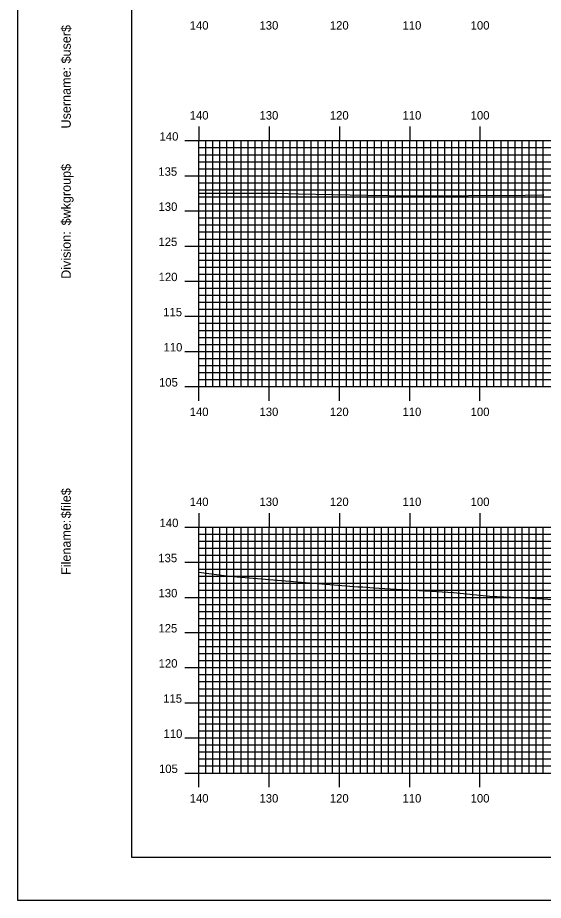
# Model space of a CAD drawing. Extents: x 1767694 to 1768037, y 442591 to 442811.
# Drawn here: x 1767693.7 to 1767768.5, y 442590.5 to 442716.2 of the extents above; entities that cross this region are included whole.
import ezdxf

# ---------------------------------------------------------------- set-up
doc = ezdxf.new("R2010")
doc.units = 0
for name, color, linetype in [('BORDER', 7, 'Continuous'), ('H_V ANNOTATION', 7, 'Continuous'), ('MAJOR', 7, 'Continuous'), ('MINOR', 7, 'Continuous'), ('PLOT BOUNDARY', 7, 'Continuous'), ('S_Roadway_Centerline', 7, 'Continuous')]:
    doc.layers.add(name, color=color, linetype=linetype)

msp = doc.modelspace()

# ---------------------------------------------------------------- linework, layer by layer
at = {"layer": 'BORDER'}
msp.add_lwpolyline([(1767709.85, 442596.67), (1768029.85, 442596.67), (1768029.85, 442806.67), (1767709.85, 442806.67)], close=True, dxfattribs=at)
at = {"layer": 'MAJOR'}
for p, q in [((1767719.45, 442700.67), (1767719.45, 442698.67)), ((1767729.45, 442700.67), (1767729.45, 442698.67)), ((1767739.45, 442700.67), (1767739.45, 442698.67)), ((1767749.45, 442700.67), (1767749.45, 442698.67)), ((1767759.45, 442700.67), (1767759.45, 442698.67)), ((1767717.45, 442698.67), (1767719.45, 442698.67)), ((1767719.45, 442698.67), (1767999.45, 442698.67)), ((1767719.45, 442663.67), (1767719.45, 442698.67)), ((1767719.45, 442663.67), (1767719.45, 442698.67)), ((1767719.45, 442698.67), (1767999.45, 442698.67)), ((1767729.45, 442663.67), (1767729.45, 442698.67)), ((1767739.45, 442663.67), (1767739.45, 442698.67)), ((1767749.45, 442663.67), (1767749.45, 442698.67)), ((1767759.45, 442663.67), (1767759.45, 442698.67)), ((1767717.45, 442693.67), (1767719.45, 442693.67)), ((1767719.45, 442693.67), (1767999.45, 442693.67)), ((1767717.45, 442688.67), (1767719.45, 442688.67)), ((1767719.45, 442688.67), (1767999.45, 442688.67)), ((1767717.45, 442683.67), (1767719.45, 442683.67)), ((1767719.45, 442683.67), (1767999.45, 442683.67)), ((1767717.45, 442678.67), (1767719.45, 442678.67)), ((1767719.45, 442678.67), (1767999.45, 442678.67)), ((1767717.45, 442673.67), (1767719.45, 442673.67)), ((1767719.45, 442673.67), (1767999.45, 442673.67)), ((1767717.45, 442668.67), (1767719.45, 442668.67)), ((1767719.45, 442668.67), (1767999.45, 442668.67)), ((1767717.45, 442663.67), (1767719.45, 442663.67)), ((1767719.45, 442663.67), (1767999.45, 442663.67)), ((1767719.45, 442663.67), (1767999.45, 442663.67)), ((1767719.45, 442661.66), (1767719.45, 442663.67)), ((1767729.45, 442661.66), (1767729.45, 442663.67)), ((1767739.45, 442661.66), (1767739.45, 442663.67)), ((1767749.45, 442661.66), (1767749.45, 442663.67)), ((1767759.45, 442661.66), (1767759.45, 442663.67)), ((1767719.45, 442645.67), (1767719.45, 442643.67)), ((1767729.45, 442645.67), (1767729.45, 442643.67)), ((1767739.45, 442645.67), (1767739.45, 442643.67)), ((1767749.45, 442645.67), (1767749.45, 442643.67)), ((1767759.45, 442645.67), (1767759.45, 442643.67)), ((1767717.45, 442643.67), (1767719.45, 442643.67)), ((1767719.45, 442643.67), (1767999.45, 442643.67)), ((1767719.45, 442608.67), (1767719.45, 442643.67)), ((1767719.45, 442608.67), (1767719.45, 442643.67)), ((1767719.45, 442643.67), (1767999.45, 442643.67)), ((1767729.45, 442608.67), (1767729.45, 442643.67)), ((1767739.45, 442608.67), (1767739.45, 442643.67)), ((1767749.45, 442608.67), (1767749.45, 442643.67)), ((1767759.45, 442608.67), (1767759.45, 442643.67)), ((1767717.45, 442638.67), (1767719.45, 442638.67)), ((1767719.45, 442638.67), (1767999.45, 442638.67)), ((1767717.45, 442633.67), (1767719.45, 442633.67)), ((1767719.45, 442633.67), (1767999.45, 442633.67)), ((1767717.45, 442628.67), (1767719.45, 442628.67)), ((1767719.45, 442628.67), (1767999.45, 442628.67)), ((1767717.45, 442623.67), (1767719.45, 442623.67)), ((1767719.45, 442623.67), (1767999.45, 442623.67)), ((1767717.45, 442618.67), (1767719.45, 442618.67)), ((1767719.45, 442618.67), (1767999.45, 442618.67)), ((1767717.45, 442613.67), (1767719.45, 442613.67)), ((1767719.45, 442613.67), (1767999.45, 442613.67)), ((1767717.45, 442608.67), (1767719.45, 442608.67)), ((1767719.45, 442608.67), (1767999.45, 442608.67)), ((1767719.45, 442608.67), (1767999.45, 442608.67)), ((1767719.45, 442606.66), (1767719.45, 442608.67)), ((1767729.45, 442606.66), (1767729.45, 442608.67)), ((1767739.45, 442606.66), (1767739.45, 442608.67)), ((1767749.45, 442606.66), (1767749.45, 442608.67)), ((1767759.45, 442606.66), (1767759.45, 442608.67))]:
    msp.add_line(p, q, dxfattribs=at)
at = {"layer": 'MINOR'}
for p, q in [((1767720.45, 442663.67), (1767720.45, 442698.67)), ((1767721.45, 442663.67), (1767721.45, 442698.67)), ((1767722.45, 442663.67), (1767722.45, 442698.67)), ((1767723.45, 442663.67), (1767723.45, 442698.67)), ((1767724.45, 442663.67), (1767724.45, 442698.67)), ((1767725.45, 442663.67), (1767725.45, 442698.67)), ((1767726.45, 442663.67), (1767726.45, 442698.67)), ((1767727.45, 442663.67), (1767727.45, 442698.67)), ((1767728.45, 442663.67), (1767728.45, 442698.67)), ((1767730.45, 442663.67), (1767730.45, 442698.67)), ((1767731.45, 442663.67), (1767731.45, 442698.67)), ((1767732.45, 442663.67), (1767732.45, 442698.67)), ((1767733.45, 442663.67), (1767733.45, 442698.67)), ((1767734.45, 442663.67), (1767734.45, 442698.67)), ((1767735.45, 442663.67), (1767735.45, 442698.67)), ((1767736.45, 442663.67), (1767736.45, 442698.67)), ((1767737.45, 442663.67), (1767737.45, 442698.67)), ((1767738.45, 442663.67), (1767738.45, 442698.67)), ((1767740.45, 442663.67), (1767740.45, 442698.67)), ((1767741.45, 442663.67), (1767741.45, 442698.67)), ((1767742.45, 442663.67), (1767742.45, 442698.67)), ((1767743.45, 442663.67), (1767743.45, 442698.67)), ((1767744.45, 442663.67), (1767744.45, 442698.67)), ((1767745.45, 442663.67), (1767745.45, 442698.67)), ((1767746.45, 442663.67), (1767746.45, 442698.67)), ((1767747.45, 442663.67), (1767747.45, 442698.67)), ((1767748.45, 442663.67), (1767748.45, 442698.67)), ((1767750.45, 442663.67), (1767750.45, 442698.67)), ((1767751.45, 442663.67), (1767751.45, 442698.67)), ((1767752.45, 442663.67), (1767752.45, 442698.67)), ((1767753.45, 442663.67), (1767753.45, 442698.67)), ((1767754.45, 442663.67), (1767754.45, 442698.67)), ((1767755.45, 442663.67), (1767755.45, 442698.67)), ((1767756.45, 442663.67), (1767756.45, 442698.67)), ((1767757.45, 442663.67), (1767757.45, 442698.67)), ((1767758.45, 442663.67), (1767758.45, 442698.67)), ((1767760.45, 442663.67), (1767760.45, 442698.67)), ((1767761.45, 442663.67), (1767761.45, 442698.67)), ((1767762.45, 442663.67), (1767762.45, 442698.67)), ((1767763.45, 442663.67), (1767763.45, 442698.67)), ((1767764.45, 442663.67), (1767764.45, 442698.67)), ((1767765.45, 442663.67), (1767765.45, 442698.67)), ((1767766.45, 442663.67), (1767766.45, 442698.67)), ((1767767.45, 442663.67), (1767767.45, 442698.67)), ((1767768.45, 442663.67), (1767768.45, 442698.67)), ((1767719.45, 442697.67), (1767999.45, 442697.67)), ((1767719.45, 442697.67), (1767721.45, 442697.67)), ((1767719.45, 442696.67), (1767999.45, 442696.67)), ((1767719.45, 442696.67), (1767721.45, 442696.67)), ((1767719.45, 442695.67), (1767999.45, 442695.67)), ((1767719.45, 442695.67), (1767721.45, 442695.67)), ((1767719.45, 442694.67), (1767999.45, 442694.67)), ((1767719.45, 442694.67), (1767721.45, 442694.67)), ((1767719.45, 442692.67), (1767999.45, 442692.67)), ((1767719.45, 442692.67), (1767721.45, 442692.67)), ((1767719.45, 442691.67), (1767999.45, 442691.67)), ((1767719.45, 442691.67), (1767721.45, 442691.67)), ((1767719.45, 442690.67), (1767999.45, 442690.67)), ((1767719.45, 442690.67), (1767721.45, 442690.67)), ((1767719.45, 442689.67), (1767999.45, 442689.67)), ((1767719.45, 442689.67), (1767721.45, 442689.67)), ((1767719.45, 442687.67), (1767999.45, 442687.67)), ((1767719.45, 442687.67), (1767721.45, 442687.67)), ((1767719.45, 442686.67), (1767999.45, 442686.67)), ((1767719.45, 442686.67), (1767721.45, 442686.67)), ((1767719.45, 442685.67), (1767999.45, 442685.67)), ((1767719.45, 442685.67), (1767721.45, 442685.67)), ((1767719.45, 442684.67), (1767999.45, 442684.67)), ((1767719.45, 442684.67), (1767721.45, 442684.67)), ((1767719.45, 442682.67), (1767999.45, 442682.67)), ((1767719.45, 442682.67), (1767721.45, 442682.67)), ((1767719.45, 442681.67), (1767999.45, 442681.67)), ((1767719.45, 442681.67), (1767721.45, 442681.67)), ((1767719.45, 442680.67), (1767999.45, 442680.67)), ((1767719.45, 442680.67), (1767721.45, 442680.67)), ((1767719.45, 442679.67), (1767999.45, 442679.67)), ((1767719.45, 442679.67), (1767721.45, 442679.67)), ((1767719.45, 442677.67), (1767999.45, 442677.67)), ((1767719.45, 442677.67), (1767721.45, 442677.67)), ((1767719.45, 442676.67), (1767999.45, 442676.67)), ((1767719.45, 442676.67), (1767721.45, 442676.67)), ((1767719.45, 442675.67), (1767999.45, 442675.67)), ((1767719.45, 442675.67), (1767721.45, 442675.67)), ((1767719.45, 442674.67), (1767999.45, 442674.67)), ((1767719.45, 442674.67), (1767721.45, 442674.67)), ((1767719.45, 442672.67), (1767999.45, 442672.67)), ((1767719.45, 442672.67), (1767721.45, 442672.67)), ((1767719.45, 442671.67), (1767999.45, 442671.67)), ((1767719.45, 442671.67), (1767721.45, 442671.67)), ((1767719.45, 442670.67), (1767999.45, 442670.67)), ((1767719.45, 442670.67), (1767721.45, 442670.67)), ((1767719.45, 442669.67), (1767999.45, 442669.67)), ((1767719.45, 442669.67), (1767721.45, 442669.67)), ((1767719.45, 442667.67), (1767999.45, 442667.67)), ((1767719.45, 442667.67), (1767721.45, 442667.67)), ((1767719.45, 442666.67), (1767999.45, 442666.67)), ((1767719.45, 442666.67), (1767721.45, 442666.67)), ((1767719.45, 442665.67), (1767999.45, 442665.67)), ((1767719.45, 442665.67), (1767721.45, 442665.67)), ((1767719.45, 442664.67), (1767999.45, 442664.67)), ((1767719.45, 442664.67), (1767721.45, 442664.67)), ((1767720.45, 442608.67), (1767720.45, 442643.67)), ((1767721.45, 442608.67), (1767721.45, 442643.67)), ((1767722.45, 442608.67), (1767722.45, 442643.67)), ((1767723.45, 442608.67), (1767723.45, 442643.67)), ((1767724.45, 442608.67), (1767724.45, 442643.67)), ((1767725.45, 442608.67), (1767725.45, 442643.67)), ((1767726.45, 442608.67), (1767726.45, 442643.67)), ((1767727.45, 442608.67), (1767727.45, 442643.67)), ((1767728.45, 442608.67), (1767728.45, 442643.67)), ((1767730.45, 442608.67), (1767730.45, 442643.67)), ((1767731.45, 442608.67), (1767731.45, 442643.67)), ((1767732.45, 442608.67), (1767732.45, 442643.67)), ((1767733.45, 442608.67), (1767733.45, 442643.67)), ((1767734.45, 442608.67), (1767734.45, 442643.67)), ((1767735.45, 442608.67), (1767735.45, 442643.67)), ((1767736.45, 442608.67), (1767736.45, 442643.67)), ((1767737.45, 442608.67), (1767737.45, 442643.67)), ((1767738.45, 442608.67), (1767738.45, 442643.67)), ((1767740.45, 442608.67), (1767740.45, 442643.67)), ((1767741.45, 442608.67), (1767741.45, 442643.67)), ((1767742.45, 442608.67), (1767742.45, 442643.67)), ((1767743.45, 442608.67), (1767743.45, 442643.67)), ((1767744.45, 442608.67), (1767744.45, 442643.67)), ((1767745.45, 442608.67), (1767745.45, 442643.67)), ((1767746.45, 442608.67), (1767746.45, 442643.67)), ((1767747.45, 442608.67), (1767747.45, 442643.67)), ((1767748.45, 442608.67), (1767748.45, 442643.67)), ((1767750.45, 442608.67), (1767750.45, 442643.67)), ((1767751.45, 442608.67), (1767751.45, 442643.67)), ((1767752.45, 442608.67), (1767752.45, 442643.67)), ((1767753.45, 442608.67), (1767753.45, 442643.67)), ((1767754.45, 442608.67), (1767754.45, 442643.67)), ((1767755.45, 442608.67), (1767755.45, 442643.67)), ((1767756.45, 442608.67), (1767756.45, 442643.67)), ((1767757.45, 442608.67), (1767757.45, 442643.67)), ((1767758.45, 442608.67), (1767758.45, 442643.67)), ((1767760.45, 442608.67), (1767760.45, 442643.67)), ((1767761.45, 442608.67), (1767761.45, 442643.67)), ((1767762.45, 442608.67), (1767762.45, 442643.67)), ((1767763.45, 442608.67), (1767763.45, 442643.67)), ((1767764.45, 442608.67), (1767764.45, 442643.67)), ((1767765.45, 442608.67), (1767765.45, 442643.67)), ((1767766.45, 442608.67), (1767766.45, 442643.67)), ((1767767.45, 442608.67), (1767767.45, 442643.67)), ((1767768.45, 442608.67), (1767768.45, 442643.67)), ((1767719.45, 442642.67), (1767999.45, 442642.67)), ((1767719.45, 442642.67), (1767721.45, 442642.67)), ((1767719.45, 442641.67), (1767999.45, 442641.67)), ((1767719.45, 442641.67), (1767721.45, 442641.67)), ((1767719.45, 442640.67), (1767999.45, 442640.67)), ((1767719.45, 442640.67), (1767721.45, 442640.67)), ((1767719.45, 442639.67), (1767999.45, 442639.67)), ((1767719.45, 442639.67), (1767721.45, 442639.67)), ((1767719.45, 442637.67), (1767999.45, 442637.67)), ((1767719.45, 442637.67), (1767721.45, 442637.67)), ((1767719.45, 442636.67), (1767999.45, 442636.67)), ((1767719.45, 442636.67), (1767721.45, 442636.67)), ((1767719.45, 442635.67), (1767999.45, 442635.67)), ((1767719.45, 442635.67), (1767721.45, 442635.67)), ((1767719.45, 442634.67), (1767999.45, 442634.67)), ((1767719.45, 442634.67), (1767721.45, 442634.67)), ((1767719.45, 442632.67), (1767999.45, 442632.67)), ((1767719.45, 442632.67), (1767721.45, 442632.67)), ((1767719.45, 442631.67), (1767999.45, 442631.67)), ((1767719.45, 442631.67), (1767721.45, 442631.67)), ((1767719.45, 442630.67), (1767999.45, 442630.67)), ((1767719.45, 442630.67), (1767721.45, 442630.67)), ((1767719.45, 442629.67), (1767999.45, 442629.67)), ((1767719.45, 442629.67), (1767721.45, 442629.67)), ((1767719.45, 442627.67), (1767999.45, 442627.67)), ((1767719.45, 442627.67), (1767721.45, 442627.67)), ((1767719.45, 442626.67), (1767999.45, 442626.67)), ((1767719.45, 442626.67), (1767721.45, 442626.67)), ((1767719.45, 442625.67), (1767999.45, 442625.67)), ((1767719.45, 442625.67), (1767721.45, 442625.67)), ((1767719.45, 442624.67), (1767999.45, 442624.67)), ((1767719.45, 442624.67), (1767721.45, 442624.67)), ((1767719.45, 442622.67), (1767999.45, 442622.67)), ((1767719.45, 442622.67), (1767721.45, 442622.67)), ((1767719.45, 442621.67), (1767999.45, 442621.67)), ((1767719.45, 442621.67), (1767721.45, 442621.67)), ((1767719.45, 442620.67), (1767999.45, 442620.67)), ((1767719.45, 442620.67), (1767721.45, 442620.67)), ((1767719.45, 442619.67), (1767999.45, 442619.67)), ((1767719.45, 442619.67), (1767721.45, 442619.67)), ((1767719.45, 442617.67), (1767999.45, 442617.67)), ((1767719.45, 442617.67), (1767721.45, 442617.67)), ((1767719.45, 442616.67), (1767999.45, 442616.67)), ((1767719.45, 442616.67), (1767721.45, 442616.67)), ((1767719.45, 442615.67), (1767999.45, 442615.67)), ((1767719.45, 442615.67), (1767721.45, 442615.67)), ((1767719.45, 442614.67), (1767999.45, 442614.67)), ((1767719.45, 442614.67), (1767721.45, 442614.67)), ((1767719.45, 442612.67), (1767999.45, 442612.67)), ((1767719.45, 442612.67), (1767721.45, 442612.67)), ((1767719.45, 442611.67), (1767999.45, 442611.67)), ((1767719.45, 442611.67), (1767721.45, 442611.67)), ((1767719.45, 442610.67), (1767999.45, 442610.67)), ((1767719.45, 442610.67), (1767721.45, 442610.67)), ((1767719.45, 442609.67), (1767999.45, 442609.67)), ((1767719.45, 442609.67), (1767721.45, 442609.67))]:
    msp.add_line(p, q, dxfattribs=at)
at = {"layer": 'PLOT BOUNDARY'}
msp.add_lwpolyline([(1767693.66, 442590.55), (1768033.66, 442590.55), (1768033.66, 442810.55), (1767693.66, 442810.55)], close=True, dxfattribs=at)
at = {"layer": 'S_Roadway_Centerline'}
for points in [[(1767719.45, 442691.21), (1767719.94, 442691.21), (1767730.63, 442691.18), (1767733.65, 442691.12), (1767743.4, 442690.92), (1767749.69, 442690.8), (1767765.88, 442690.93), (1767768.54, 442690.94)], [(1767719.45, 442637.27), (1767723.76, 442636.7), (1767739.24, 442635.38), (1767742.08, 442635.18), (1767742.78, 442635.16), (1767744.29, 442635.04), (1767755.69, 442634.36), (1767760.84, 442633.83), (1767766.88, 442633.56), (1767778.05, 442632.86)]]:
    msp.add_lwpolyline(points, dxfattribs=at)

# ---------------------------------------------------------------- texts
at = {"layer": 'BORDER'}
for s, p in [('$user$', (1767701.22, 442709.65)), ('Username:', (1767701.22, 442700.4)), ('$wkgroup$', (1767701.22, 442686.6)), ('Division:', (1767701.22, 442679)), ('$file$', (1767701.22, 442644.92)), ('Filename:', (1767701.22, 442636.86))]:
    msp.add_text(s, height=1.339, rotation=90, dxfattribs=at).set_placement(p)
at = {"layer": 'H_V ANNOTATION'}
for s, p in [('140', (1767718.15, 442714.47)), ('130', (1767728.08, 442714.47)), ('120', (1767738.09, 442714.47)), ('110', (1767748.43, 442714.47)), ('100', (1767758.13, 442714.47)), ('140', (1767718.15, 442701.67)), ('130', (1767728.08, 442701.67)), ('120', (1767738.09, 442701.67)), ('110', (1767748.43, 442701.67)), ('100', (1767758.13, 442701.67)), ('140', (1767713.86, 442698.67)), ('135', (1767713.68, 442693.67)), ('130', (1767713.71, 442688.67)), ('125', (1767713.7, 442683.67)), ('120', (1767713.73, 442678.67)), ('115', (1767714.38, 442673.67)), ('110', (1767714.42, 442668.67)), ('105', (1767713.78, 442663.67)), ('140', (1767718.15, 442659.47)), ('130', (1767728.08, 442659.47)), ('120', (1767738.09, 442659.47)), ('110', (1767748.43, 442659.47)), ('100', (1767758.13, 442659.47)), ('140', (1767718.15, 442646.67)), ('130', (1767728.08, 442646.67)), ('120', (1767738.09, 442646.67)), ('110', (1767748.43, 442646.67)), ('100', (1767758.13, 442646.67)), ('140', (1767713.86, 442643.67)), ('135', (1767713.68, 442638.67)), ('130', (1767713.71, 442633.67)), ('125', (1767713.7, 442628.67)), ('120', (1767713.73, 442623.67)), ('115', (1767714.38, 442618.67)), ('110', (1767714.42, 442613.67)), ('105', (1767713.78, 442608.67)), ('140', (1767718.15, 442604.47)), ('130', (1767728.08, 442604.47)), ('120', (1767738.09, 442604.47)), ('110', (1767748.43, 442604.47)), ('100', (1767758.13, 442604.47))]:
    msp.add_text(s, height=1.2, dxfattribs=at).set_placement(p)
at = {"layer": 'MAJOR'}
for p in [(1767719.44, 442663.67), (1767719.44, 442608.67)]:
    msp.add_text('-', height=0.012, dxfattribs=at).set_placement(p)

doc.saveas('drawing.dxf')
